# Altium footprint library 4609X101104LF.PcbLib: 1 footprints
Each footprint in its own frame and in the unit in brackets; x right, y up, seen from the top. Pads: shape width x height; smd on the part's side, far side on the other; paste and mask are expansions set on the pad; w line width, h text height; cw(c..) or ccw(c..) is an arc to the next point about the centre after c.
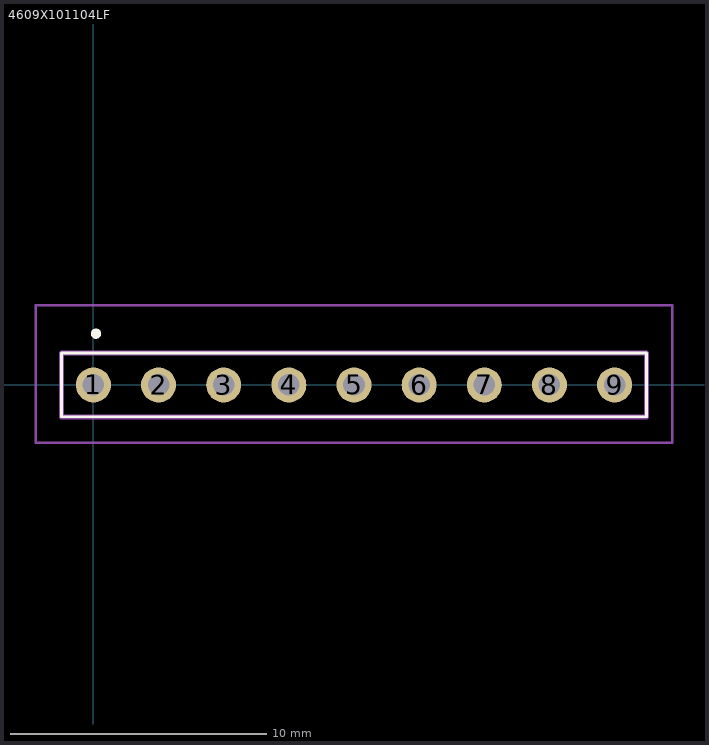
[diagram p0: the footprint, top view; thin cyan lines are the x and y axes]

## 4609X101104LF [mm]
pads (9):
  round 1.365 hole 0.84: 1(0,0) 2(2.54,0) 3(5.08,0) 4(7.62,0) 5(10.16,0) 6(12.7,0) 7(15.24,0) 8(17.78,0) 9(20.32,0)
Top Overlay:
  lines w0.1: -1.245,-1.245 21.565,-1.245 21.565,1.245 -1.245,1.245 -1.245,-1.245
  lines w0.2: 0,2 0,2 ; 0,2 ccw(c0.1,2) 0.2,2 ; 0,2 cw(c0.1,2) 0.2,2 ; 0.2,2 0.2,2
Mechanical 15:
  lines w0.2: -1.245,-1.245 21.565,-1.245 21.565,1.245 -1.245,1.245 -1.245,-1.245
Mechanical 20:
  lines w0.1: -2.245,-2.245 22.565,-2.245 22.565,3.1 -2.245,3.1 -2.245,-2.245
